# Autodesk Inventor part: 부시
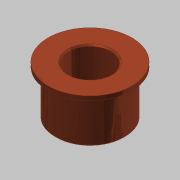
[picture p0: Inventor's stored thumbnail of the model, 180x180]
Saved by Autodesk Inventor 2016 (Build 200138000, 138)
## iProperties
Created: 2015-10
Part Number: 부시
Document SubType Name: Modeling
Designer: mdu
Density: 7.86 g/cm^3
Material: 강철, 연강
Mass: 364.706 g
Surface Area: 129.307 cm^2
Volume: 46.4003 cm^3
Appearance: 구리 - 새틴
Author: mdu
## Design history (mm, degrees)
sketch "스케치1"
  geometry: C1 r 31 at (0, 0) reference; C2 r 25 at (0, 0) reference; C3 r 30 at (0, 0) reference; 1 further point
  node "참조1"
  node "참조2"
  node "참조4"
extrude "돌출1" new body sketch "스케치1" distance "d0" = 3; taper "d1" = 0 deg
extrude "돌출2" join sketch "스케치1" distance "d2" = 35; taper "d3" = 0 deg
chamfer "모따기1" distance "d6" = 1; stored, may be unused: second distance "d7" = 2, angle "d8" = 45 deg
sketch "스케치3"
  geometry: C1 r 15 at (0, 0); 1 further point
  constraints: 1 centre point, 1 coincident
  dimensions: "d13" = 30 diameter of C1
extrude "돌출4" cut sketch "스케치3" stored distance "d14" = 10; taper "d15" = 0 deg
chamfer "모따기3" distance "d16" = 1; stored, may be unused: second distance "d17" = 2, angle "d18" = 45 deg
node "솔리드1"
